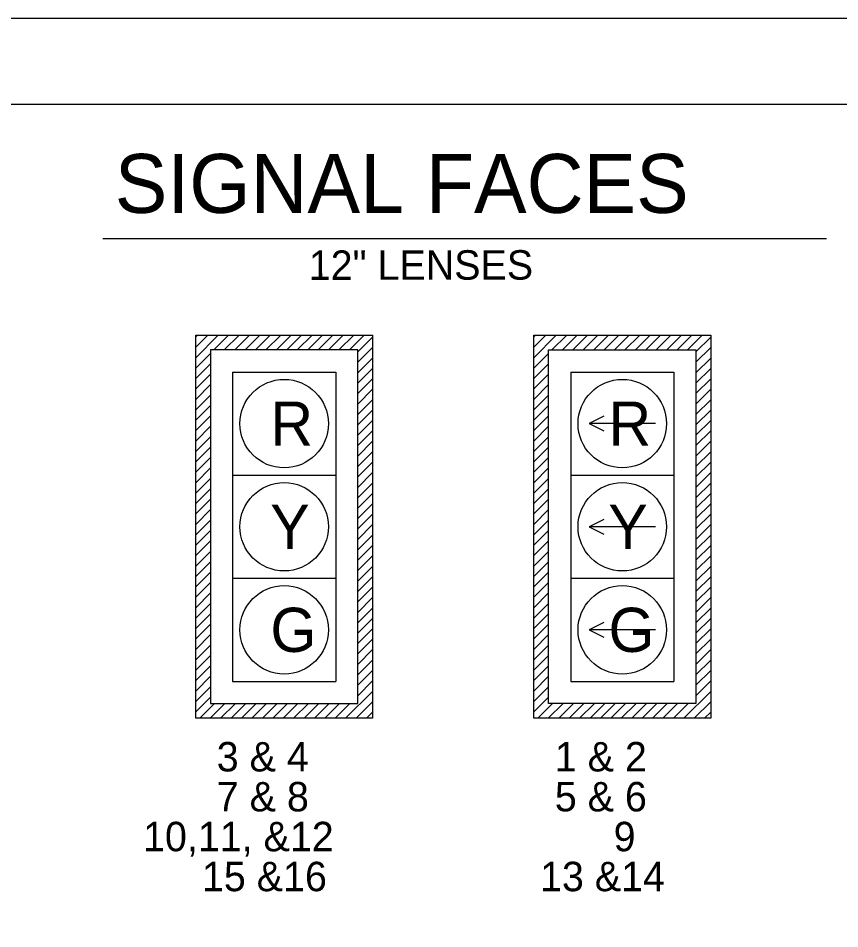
# Model space of a CAD drawing. Extents: x 635746 to 638310, y 744089 to 745312.
# Drawn here: x 635886.7 to 635979.6, y 745209 to 745312 of the extents above; entities that cross this region are included whole.
import ezdxf

# ---------------------------------------------------------------- set-up
doc = ezdxf.new("R2010")
doc.units = 0
for name, color, linetype in [('R_Border', 7, 'Continuous'), ('R_No Plot', 7, 'Continuous'), ('T_Drafting', 7, 'Continuous'), ('T_Notes', 7, 'Continuous')]:
    doc.layers.add(name, color=color, linetype=linetype)

msp = doc.modelspace()

# ---------------------------------------------------------------- linework, layer by layer
at = {"layer": 'R_Border'}
msp.add_line((635776.8, 745302.3), (636567.25, 745302.3), dxfattribs=at)
at = {"layer": 'R_No Plot'}
msp.add_line((635745.8, 745312.04), (636579.13, 745312.04), dxfattribs=at)
msp.add_lwpolyline([(635745.78, 745312.04), (636579.13, 745312.04), (636579.13, 744778.69), (635745.78, 744778.69)], close=True, dxfattribs=at)
at = {"layer": 'T_Drafting'}
for p, q in [((635906.82, 745273.63), (635909.36, 745276.17)), ((635906.82, 745274.81), (635908.18, 745276.17)), ((635906.82, 745275.99), (635907, 745276.17)), ((635906.82, 745276.17), (635926.82, 745276.17)), ((635906.82, 745232.84), (635906.82, 745276.17)), ((635908.87, 745274.5), (635910.54, 745276.17)), ((635910.05, 745274.5), (635911.72, 745276.17)), ((635911.23, 745274.5), (635912.9, 745276.17)), ((635912.41, 745274.5), (635914.07, 745276.17)), ((635913.59, 745274.5), (635915.25, 745276.17)), ((635914.76, 745274.5), (635916.43, 745276.17)), ((635915.94, 745274.5), (635917.61, 745276.17)), ((635917.12, 745274.5), (635918.79, 745276.17)), ((635918.3, 745274.5), (635919.97, 745276.17)), ((635919.48, 745274.5), (635921.15, 745276.17)), ((635920.66, 745274.5), (635922.32, 745276.17)), ((635921.84, 745274.5), (635923.5, 745276.17)), ((635923.01, 745274.5), (635924.68, 745276.17)), ((635924.19, 745274.5), (635925.86, 745276.17)), ((635925.15, 745274.28), (635926.82, 745275.95)), ((635926.82, 745276.17), (635926.82, 745232.84)), ((635945.05, 745273.63), (635947.59, 745276.17)), ((635945.05, 745274.81), (635946.41, 745276.17)), ((635945.05, 745275.99), (635945.23, 745276.17)), ((635945.05, 745276.17), (635965.05, 745276.17)), ((635945.05, 745232.84), (635945.05, 745276.17)), ((635947.1, 745274.5), (635948.77, 745276.17)), ((635948.28, 745274.5), (635949.95, 745276.17)), ((635949.46, 745274.5), (635951.13, 745276.17)), ((635950.64, 745274.5), (635952.3, 745276.17)), ((635951.82, 745274.5), (635953.48, 745276.17)), ((635952.99, 745274.5), (635954.66, 745276.17)), ((635954.17, 745274.5), (635955.84, 745276.17)), ((635955.35, 745274.5), (635957.02, 745276.17)), ((635956.53, 745274.5), (635958.2, 745276.17)), ((635957.71, 745274.5), (635959.38, 745276.17)), ((635958.89, 745274.5), (635960.55, 745276.17)), ((635960.07, 745274.5), (635961.73, 745276.17)), ((635961.24, 745274.5), (635962.91, 745276.17)), ((635962.42, 745274.5), (635964.09, 745276.17)), ((635963.38, 745274.28), (635965.05, 745275.95)), ((635965.05, 745276.17), (635965.05, 745232.84)), ((635925.15, 745273.11), (635926.82, 745274.77)), ((635963.38, 745273.11), (635965.05, 745274.77)), ((635906.82, 745272.45), (635908.49, 745274.12)), ((635925.15, 745271.93), (635926.82, 745273.59)), ((635945.05, 745272.45), (635946.72, 745274.12)), ((635963.38, 745271.93), (635965.05, 745273.59)), ((635906.82, 745271.27), (635908.49, 745272.94)), ((635925.15, 745270.75), (635926.82, 745272.42)), ((635945.05, 745271.27), (635946.72, 745272.94)), ((635963.38, 745270.75), (635965.05, 745272.42)), ((635906.82, 745270.09), (635908.49, 745271.76)), ((635910.99, 745272), (635922.65, 745272)), ((635910.99, 745272), (635910.99, 745260.34)), ((635922.65, 745272), (635922.65, 745260.34)), ((635945.05, 745270.09), (635946.72, 745271.76)), ((635949.22, 745272), (635960.88, 745272)), ((635949.22, 745272), (635949.22, 745260.34)), ((635960.88, 745272), (635960.88, 745260.34)), ((635906.82, 745268.91), (635908.49, 745270.58)), ((635925.15, 745269.57), (635926.82, 745271.24)), ((635945.05, 745268.91), (635946.72, 745270.58)), ((635963.38, 745269.57), (635965.05, 745271.24)), ((635906.82, 745267.74), (635908.49, 745269.4)), ((635925.15, 745268.39), (635926.82, 745270.06)), ((635945.05, 745267.74), (635946.72, 745269.4)), ((635963.38, 745268.39), (635965.05, 745270.06)), ((635906.82, 745266.56), (635908.49, 745268.22)), ((635925.15, 745267.21), (635926.82, 745268.88)), ((635945.05, 745266.56), (635946.72, 745268.22)), ((635963.38, 745267.21), (635965.05, 745268.88)), ((635925.15, 745266.03), (635926.82, 745267.7)), ((635963.38, 745266.03), (635965.05, 745267.7)), ((635906.82, 745265.38), (635908.49, 745267.05)), ((635925.15, 745264.86), (635926.82, 745266.52)), ((635945.05, 745265.38), (635946.72, 745267.05)), ((635958.8, 745266.17), (635951.3, 745266.17)), ((635963.38, 745264.86), (635965.05, 745266.52)), ((635906.82, 745264.2), (635908.49, 745265.87)), ((635925.15, 745263.68), (635926.82, 745265.34)), ((635945.05, 745264.2), (635946.72, 745265.87)), ((635963.38, 745263.68), (635965.05, 745265.34)), ((635906.82, 745263.02), (635908.49, 745264.69)), ((635925.15, 745262.5), (635926.82, 745264.17)), ((635945.05, 745263.02), (635946.72, 745264.69)), ((635963.38, 745262.5), (635965.05, 745264.17)), ((635906.82, 745261.84), (635908.49, 745263.51)), ((635945.05, 745261.84), (635946.72, 745263.51)), ((635906.82, 745260.66), (635908.49, 745262.33)), ((635925.15, 745261.32), (635926.82, 745262.99)), ((635945.05, 745260.66), (635946.72, 745262.33)), ((635963.38, 745261.32), (635965.05, 745262.99)), ((635906.82, 745259.49), (635908.49, 745261.15)), ((635925.15, 745260.14), (635926.82, 745261.81)), ((635945.05, 745259.49), (635946.72, 745261.15)), ((635963.38, 745260.14), (635965.05, 745261.81)), ((635906.82, 745258.31), (635908.49, 745259.97)), ((635910.99, 745260.34), (635922.65, 745260.34)), ((635910.99, 745260.34), (635910.99, 745248.67)), ((635922.65, 745260.34), (635922.65, 745248.67)), ((635925.15, 745258.96), (635926.82, 745260.63)), ((635945.05, 745258.31), (635946.72, 745259.97)), ((635949.22, 745260.34), (635960.88, 745260.34)), ((635949.22, 745260.34), (635949.22, 745248.67)), ((635960.88, 745260.34), (635960.88, 745248.67)), ((635963.38, 745258.96), (635965.05, 745260.63)), ((635925.15, 745257.78), (635926.82, 745259.45)), ((635963.38, 745257.78), (635965.05, 745259.45)), ((635906.82, 745257.13), (635908.49, 745258.8)), ((635925.15, 745256.61), (635926.82, 745258.27)), ((635945.05, 745257.13), (635946.72, 745258.8)), ((635963.38, 745256.61), (635965.05, 745258.27)), ((635906.82, 745255.95), (635908.49, 745257.62)), ((635925.15, 745255.43), (635926.82, 745257.09)), ((635945.05, 745255.95), (635946.72, 745257.62)), ((635963.38, 745255.43), (635965.05, 745257.09)), ((635906.82, 745254.77), (635908.49, 745256.44)), ((635925.15, 745254.25), (635926.82, 745255.92)), ((635945.05, 745254.77), (635946.72, 745256.44)), ((635963.38, 745254.25), (635965.05, 745255.92)), ((635906.82, 745253.59), (635908.49, 745255.26)), ((635945.05, 745253.59), (635946.72, 745255.26)), ((635906.82, 745252.42), (635908.49, 745254.08)), ((635925.15, 745253.07), (635926.82, 745254.74)), ((635945.05, 745252.42), (635946.72, 745254.08)), ((635958.8, 745254.5), (635951.3, 745254.5)), ((635963.38, 745253.07), (635965.05, 745254.74)), ((635906.82, 745251.24), (635908.49, 745252.9)), ((635925.15, 745251.89), (635926.82, 745253.56)), ((635945.05, 745251.24), (635946.72, 745252.9)), ((635963.38, 745251.89), (635965.05, 745253.56)), ((635906.82, 745250.06), (635908.49, 745251.72)), ((635925.15, 745250.71), (635926.82, 745252.38)), ((635945.05, 745250.06), (635946.72, 745251.72)), ((635963.38, 745250.71), (635965.05, 745252.38)), ((635925.15, 745249.54), (635926.82, 745251.2)), ((635963.38, 745249.54), (635965.05, 745251.2)), ((635906.82, 745248.88), (635908.49, 745250.55)), ((635925.15, 745248.36), (635926.82, 745250.02)), ((635945.05, 745248.88), (635946.72, 745250.55)), ((635963.38, 745248.36), (635965.05, 745250.02)), ((635906.82, 745247.7), (635908.49, 745249.37)), ((635910.99, 745248.67), (635922.65, 745248.67)), ((635910.99, 745248.67), (635910.99, 745237)), ((635922.65, 745248.67), (635922.65, 745237)), ((635925.15, 745247.18), (635926.82, 745248.85)), ((635945.05, 745247.7), (635946.72, 745249.37)), ((635949.22, 745248.67), (635960.88, 745248.67)), ((635949.22, 745248.67), (635949.22, 745237)), ((635960.88, 745248.67), (635960.88, 745237)), ((635963.38, 745247.18), (635965.05, 745248.85)), ((635906.82, 745246.52), (635908.49, 745248.19)), ((635925.15, 745246), (635926.82, 745247.67)), ((635945.05, 745246.52), (635946.72, 745248.19)), ((635963.38, 745246), (635965.05, 745247.67)), ((635906.82, 745245.34), (635908.49, 745247.01)), ((635945.05, 745245.34), (635946.72, 745247.01)), ((635906.82, 745244.17), (635908.49, 745245.83)), ((635925.15, 745244.82), (635926.82, 745246.49)), ((635945.05, 745244.17), (635946.72, 745245.83)), ((635963.38, 745244.82), (635965.05, 745246.49)), ((635906.82, 745242.99), (635908.49, 745244.65)), ((635925.15, 745243.64), (635926.82, 745245.31)), ((635945.05, 745242.99), (635946.72, 745244.65)), ((635963.38, 745243.64), (635965.05, 745245.31)), ((635906.82, 745241.81), (635908.49, 745243.48)), ((635925.15, 745242.46), (635926.82, 745244.13)), ((635945.05, 745241.81), (635946.72, 745243.48)), ((635963.38, 745242.46), (635965.05, 745244.13)), ((635925.15, 745241.29), (635926.82, 745242.95)), ((635958.8, 745242.84), (635951.3, 745242.84)), ((635963.38, 745241.29), (635965.05, 745242.95)), ((635906.82, 745240.63), (635908.49, 745242.3)), ((635925.15, 745240.11), (635926.82, 745241.77)), ((635945.05, 745240.63), (635946.72, 745242.3)), ((635963.38, 745240.11), (635965.05, 745241.77)), ((635906.82, 745239.45), (635908.49, 745241.12)), ((635925.15, 745238.93), (635926.82, 745240.6)), ((635945.05, 745239.45), (635946.72, 745241.12)), ((635963.38, 745238.93), (635965.05, 745240.6)), ((635906.82, 745238.27), (635908.49, 745239.94)), ((635925.15, 745237.75), (635926.82, 745239.42)), ((635945.05, 745238.27), (635946.72, 745239.94)), ((635963.38, 745237.75), (635965.05, 745239.42)), ((635906.82, 745237.09), (635908.49, 745238.76)), ((635945.05, 745237.09), (635946.72, 745238.76)), ((635906.82, 745235.92), (635908.49, 745237.58)), ((635925.15, 745236.57), (635926.82, 745238.24)), ((635945.05, 745235.92), (635946.72, 745237.58)), ((635963.38, 745236.57), (635965.05, 745238.24)), ((635906.82, 745234.74), (635908.49, 745236.4)), ((635910.99, 745237), (635922.65, 745237)), ((635925.15, 745235.39), (635926.82, 745237.06)), ((635945.05, 745234.74), (635946.72, 745236.4)), ((635949.22, 745237), (635960.88, 745237)), ((635963.38, 745235.39), (635965.05, 745237.06)), ((635906.82, 745233.56), (635908.49, 745235.23)), ((635923.77, 745232.84), (635926.82, 745235.88)), ((635945.05, 745233.56), (635946.72, 745235.23)), ((635962, 745232.84), (635965.05, 745235.88)), ((635907.27, 745232.84), (635908.94, 745234.5)), ((635908.45, 745232.84), (635910.12, 745234.5)), ((635909.63, 745232.84), (635911.3, 745234.5)), ((635910.81, 745232.84), (635912.48, 745234.5)), ((635911.99, 745232.84), (635913.66, 745234.5)), ((635913.17, 745232.84), (635914.83, 745234.5)), ((635914.35, 745232.84), (635916.01, 745234.5)), ((635915.52, 745232.84), (635917.19, 745234.5)), ((635916.7, 745232.84), (635918.37, 745234.5)), ((635917.88, 745232.84), (635919.55, 745234.5)), ((635919.06, 745232.84), (635920.73, 745234.5)), ((635920.24, 745232.84), (635921.91, 745234.5)), ((635921.42, 745232.84), (635923.08, 745234.5)), ((635922.6, 745232.84), (635924.26, 745234.5)), ((635924.95, 745232.84), (635926.82, 745234.7)), ((635945.5, 745232.84), (635947.17, 745234.5)), ((635946.68, 745232.84), (635948.35, 745234.5)), ((635947.86, 745232.84), (635949.53, 745234.5)), ((635949.04, 745232.84), (635950.71, 745234.5)), ((635950.22, 745232.84), (635951.89, 745234.5)), ((635951.4, 745232.84), (635953.06, 745234.5)), ((635952.58, 745232.84), (635954.24, 745234.5)), ((635953.75, 745232.84), (635955.42, 745234.5)), ((635954.93, 745232.84), (635956.6, 745234.5)), ((635956.11, 745232.84), (635957.78, 745234.5)), ((635957.29, 745232.84), (635958.96, 745234.5)), ((635958.47, 745232.84), (635960.13, 745234.5)), ((635959.65, 745232.84), (635961.31, 745234.5)), ((635960.83, 745232.84), (635962.49, 745234.5)), ((635963.18, 745232.84), (635965.05, 745234.7)), ((635926.13, 745232.84), (635926.82, 745233.52)), ((635964.36, 745232.84), (635965.05, 745233.52)), ((635926.82, 745232.84), (635906.82, 745232.84)), ((635965.05, 745232.84), (635945.05, 745232.84))]:
    msp.add_line(p, q, dxfattribs=at)
for points in [[(635925.15, 745234.5), (635925.15, 745274.5), (635908.49, 745274.5), (635908.49, 745234.5)], [(635946.72, 745274.5), (635963.38, 745274.5), (635963.38, 745234.5), (635946.72, 745234.5)]]:
    msp.add_lwpolyline(points, close=True, dxfattribs=at)
for points in [[(635952.97, 745267), (635951.3, 745266.17), (635952.97, 745265.34)], [(635952.97, 745255.34), (635951.3, 745254.5), (635952.97, 745253.67)], [(635952.97, 745243.67), (635951.3, 745242.84), (635952.97, 745242)]]:
    msp.add_lwpolyline(points, dxfattribs=at)
for centre in [(635916.82, 745266.17), (635955.05, 745266.17), (635916.82, 745254.5), (635955.05, 745254.5), (635916.82, 745242.84), (635955.05, 745242.84)]:
    msp.add_circle(centre, 5, dxfattribs=at)
at = {"layer": 'T_Notes'}
msp.add_line((635896.33, 745287.12), (635978.15, 745287.12), dxfattribs=at)

# ---------------------------------------------------------------- texts
at = {"layer": 'T_Drafting'}
msp.add_text('12" LENSES', height=3.333, rotation=0.072, dxfattribs=at).set_placement((635919.6, 745282.43))
for s, p in [('R', (635915.26, 745263.67)), ('R', (635953.49, 745263.67)), ('Y', (635915.24, 745252)), ('Y', (635953.47, 745252)), ('G', (635915.26, 745240.34)), ('G', (635953.49, 745240.34))]:
    msp.add_text(s, height=5, dxfattribs=at).set_placement(p)
at = {"layer": 'T_Notes'}
msp.add_text('SIGNAL FACES', height=6.6667, rotation=360, dxfattribs=at).set_placement((635897.66, 745290.01))
for s, height, p in [('3 & 4', 3.333, (635909.19, 745226.82)), ('1 & 2', 3.333, (635947.42, 745226.82)), ('7 & 8', 3.333, (635909.2, 745222.3)), ('5 & 6', 3.333, (635947.42, 745222.3)), ('10,11, &12', 3.333, (635900.86, 745217.79)), ('9', 3.33, (635954.07, 745217.79)), ('15 &16', 3.333, (635907.52, 745213.27)), ('13 &14', 3.333, (635945.75, 745213.27))]:
    msp.add_text(s, height=height, dxfattribs=at).set_placement(p)

doc.saveas('drawing.dxf')
